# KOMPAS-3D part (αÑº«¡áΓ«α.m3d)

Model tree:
1. Эскиз:1
2. Операция выдавливания:36
     Толщина стенки 1 = 2; Толщина стенки 2 = 6; Расстояние 1 = 1; Расстояние 2 = 3
3. Эскиз:38
4. Операция выдавливания:40
     Толщина стенки 1 = 2; Толщина стенки 2 = 6; Расстояние 1 = 5; Расстояние 2 = 3
5. Эскиз:39
6. Операция выдавливания:41
     Толщина стенки 1 = 2; Толщина стенки 2 = 6; Расстояние 1 = 1; Расстояние 2 = 3
7. Эскиз:40
8. Операция выдавливания:42
     Толщина стенки 1 = 2; Толщина стенки 2 = 2.5; Расстояние 1 = 50; Расстояние 2 = 3
9. Эскиз:41
10. Вырезать элемент выдавливания:4
     Толщина стенки 2 = 1.5; Расстояние 1 = 40
11. Эскиз:42
12. Операция выдавливания:43
     Толщина стенки 1 = 2; Толщина стенки 2 = 2.5; Расстояние 1 = 50; Расстояние 2 = 3
13. Эскиз:43
14. Вырезать элемент выдавливания:5
     Толщина стенки 2 = 1.5; Расстояние 1 = 40
15. Эскиз:44
16. Операция выдавливания:44
     Толщина стенки 1 = 2; Толщина стенки 2 = 2.5; Расстояние 1 = 10; Расстояние 2 = 3
17. Эскиз:45
18. Эскиз:46
19. Операция выдавливания:47
     Толщина стенки 1 = 2; Толщина стенки 2 = 6; Расстояние 1 = 1; Расстояние 2 = 3
20. Эскиз:47
21. Операция выдавливания:48
     Толщина стенки 1 = 2; Толщина стенки 2 = 6; Расстояние 1 = 5; Расстояние 2 = 3
22. Эскиз:48
23. Операция выдавливания:49
     Толщина стенки 1 = 2; Толщина стенки 2 = 6; Расстояние 1 = 1; Расстояние 2 = 3
24. Эскиз:49
25. Вырезать элемент выдавливания:6
     Толщина стенки 2 = 1.5; Расстояние 1 = 22
26. Эскиз:50
27. Вырезать элемент выдавливания:7
     Толщина стенки 2 = 1.5; Расстояние 1 = 1
